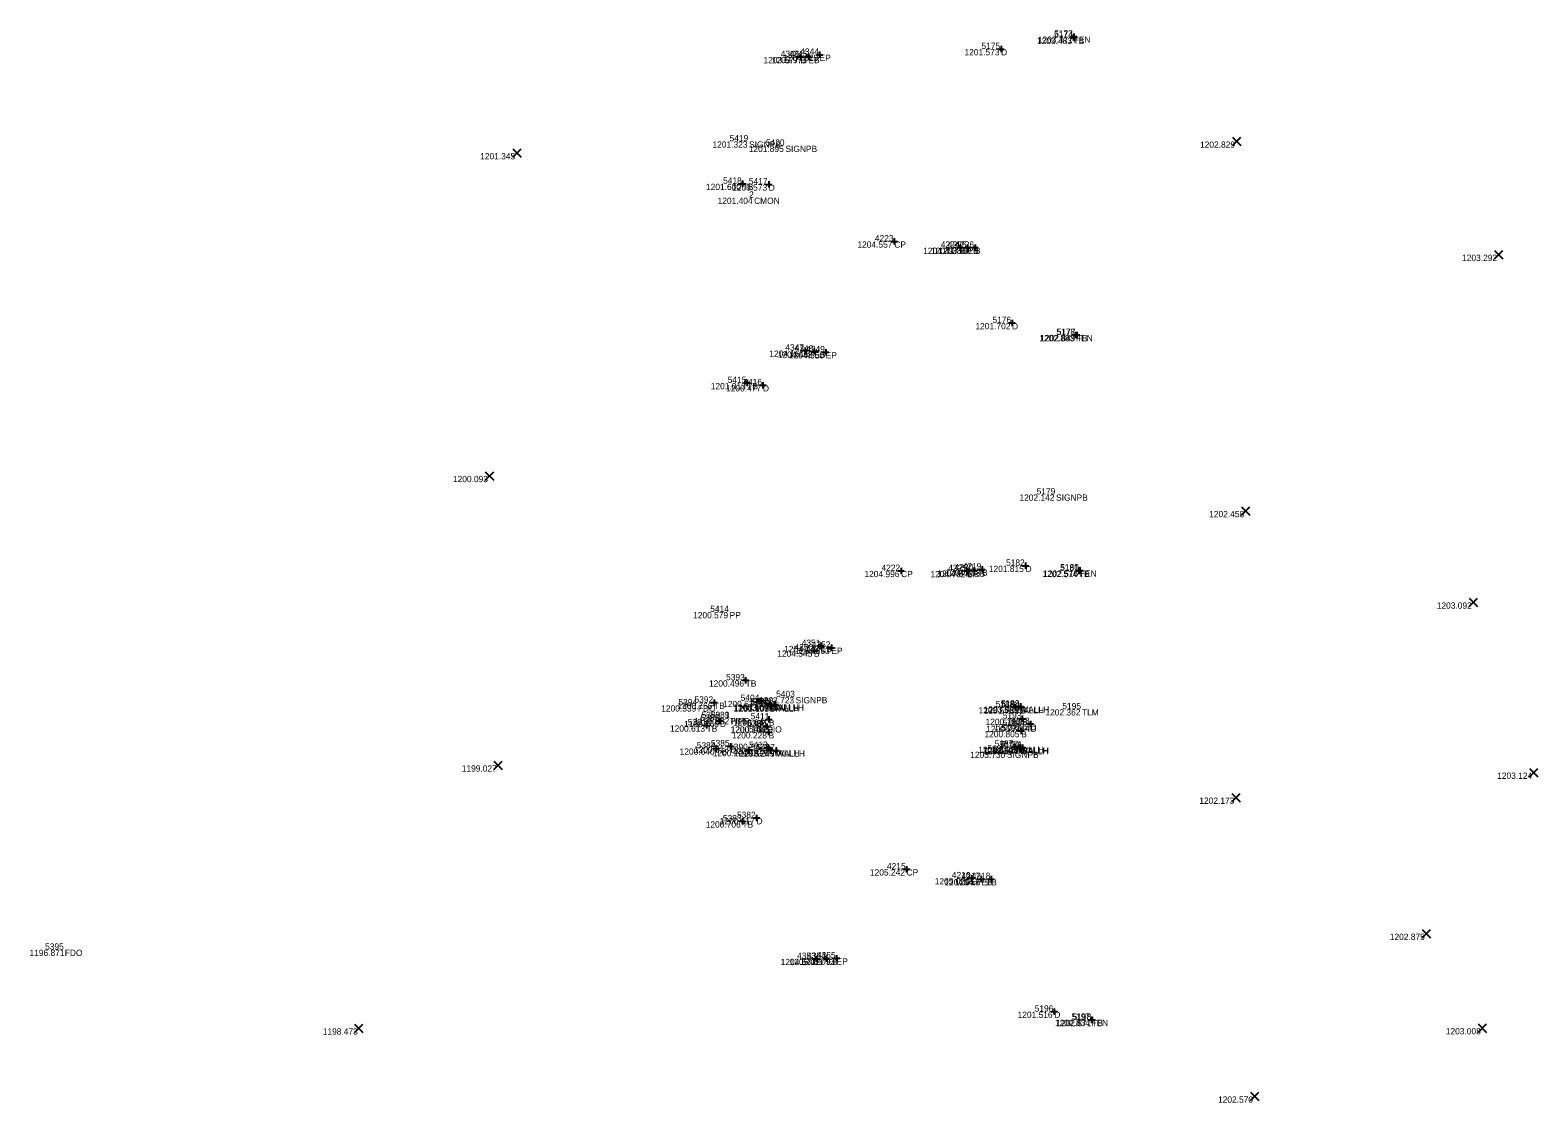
# Model space of a CAD drawing. Extents: x 2044997 to 2050342, y 455233 to 458054.
# Drawn here: x 2047488.9 to 2047729, y 457177 to 457347.8 of the extents above; entities that cross this region are included whole.
import ezdxf

# ---------------------------------------------------------------- set-up
doc = ezdxf.new("R2010")
doc.units = 0
for name, color, linetype in [('SV_X_Random_Point', 7, 'Continuous'), ('SV_X_Shot_Marker', 7, 'Continuous'), ('SV_X_Text_Comment', 7, 'Continuous'), ('SV_X_Text_Elevation', 7, 'Continuous'), ('SV_X_Text_Name', 7, 'Continuous')]:
    doc.layers.add(name, color=color, linetype=linetype)

msp = doc.modelspace()

# ---------------------------------------------------------------- linework, layer by layer
at = {"layer": 'SV_X_Random_Point'}
for p, q in [((2047680.37, 457329.41), (2047681.7, 457330.74)), ((2047680.37, 457330.74), (2047681.7, 457329.41)), ((2047565.73, 457327.55), (2047567.07, 457328.88)), ((2047565.73, 457328.88), (2047567.07, 457327.55)), ((2047722.14, 457311.4), (2047723.47, 457312.73)), ((2047722.14, 457312.73), (2047723.47, 457311.4)), ((2047561.37, 457276.15), (2047562.71, 457277.48)), ((2047561.37, 457277.48), (2047562.71, 457276.15)), ((2047681.85, 457270.57), (2047683.18, 457271.9)), ((2047681.85, 457271.9), (2047683.18, 457270.57)), ((2047718.1, 457256), (2047719.43, 457257.34)), ((2047718.1, 457257.34), (2047719.43, 457256)), ((2047562.72, 457230.05), (2047564.05, 457231.38)), ((2047562.72, 457231.38), (2047564.05, 457230.05)), ((2047727.7, 457228.9), (2047729.04, 457230.24)), ((2047727.7, 457230.24), (2047729.04, 457228.9)), ((2047680.27, 457224.92), (2047681.6, 457226.26)), ((2047680.27, 457226.26), (2047681.6, 457224.92)), ((2047710.63, 457203.24), (2047711.96, 457204.58)), ((2047710.63, 457204.58), (2047711.96, 457203.24)), ((2047540.53, 457188.16), (2047541.86, 457189.5)), ((2047540.53, 457189.5), (2047541.86, 457188.16)), ((2047719.54, 457188.2), (2047720.87, 457189.53)), ((2047719.54, 457189.53), (2047720.87, 457188.2)), ((2047683.26, 457177.32), (2047684.6, 457178.65)), ((2047683.26, 457178.65), (2047684.6, 457177.32))]:
    msp.add_line(p, q, dxfattribs=at)
at = {"layer": 'SV_X_Shot_Marker'}
for p, q in [((2047654.57, 457346.6), (2047655.57, 457346.6)), ((2047654.6, 457346.79), (2047655.6, 457346.79)), ((2047655.07, 457347.1), (2047655.07, 457346.1)), ((2047655.07, 457346.6), (2047655.07, 457346.6)), ((2047655.1, 457347.29), (2047655.1, 457346.29)), ((2047655.1, 457346.79), (2047655.1, 457346.79)), ((2047611.06, 457343.54), (2047612.06, 457343.54)), ((2047611.56, 457344.04), (2047611.56, 457343.04)), ((2047611.56, 457343.54), (2047611.56, 457343.54)), ((2047612.35, 457343.54), (2047613.35, 457343.54)), ((2047612.85, 457344.04), (2047612.85, 457343.04)), ((2047612.85, 457343.54), (2047612.85, 457343.54)), ((2047614.13, 457343.89), (2047615.13, 457343.89)), ((2047614.63, 457344.39), (2047614.63, 457343.39)), ((2047614.63, 457343.89), (2047614.63, 457343.89)), ((2047643.03, 457344.79), (2047644.03, 457344.79)), ((2047643.53, 457345.29), (2047643.53, 457344.29)), ((2047643.53, 457344.79), (2047643.53, 457344.79)), ((2047601.86, 457323.34), (2047602.86, 457323.34)), ((2047602.36, 457323.84), (2047602.36, 457322.84)), ((2047602.36, 457323.34), (2047602.36, 457323.34)), ((2047606.01, 457323.24), (2047607.01, 457323.24)), ((2047606.51, 457323.74), (2047606.51, 457322.74)), ((2047606.51, 457323.24), (2047606.51, 457323.24)), ((2047626.52, 457314.66), (2047626.52, 457313.66)), ((2047626.02, 457314.16), (2047627.02, 457314.16)), ((2047626.52, 457314.16), (2047626.52, 457314.16)), ((2047636.51, 457313.17), (2047637.51, 457313.17)), ((2047637.01, 457313.67), (2047637.01, 457312.67)), ((2047637.01, 457313.17), (2047637.01, 457313.17)), ((2047637.68, 457313.17), (2047638.68, 457313.17)), ((2047638.18, 457313.67), (2047638.18, 457312.67)), ((2047638.18, 457313.17), (2047638.18, 457313.17)), ((2047638.88, 457313.17), (2047639.88, 457313.17)), ((2047639.38, 457313.67), (2047639.38, 457312.67)), ((2047639.38, 457313.17), (2047639.38, 457313.17)), ((2047644.77, 457301.17), (2047645.77, 457301.17)), ((2047645.27, 457301.67), (2047645.27, 457300.67)), ((2047645.27, 457301.17), (2047645.27, 457301.17)), ((2047654.96, 457299.25), (2047655.96, 457299.25)), ((2047655.08, 457299.27), (2047656.08, 457299.27)), ((2047655.46, 457299.75), (2047655.46, 457298.75)), ((2047655.46, 457299.25), (2047655.46, 457299.25)), ((2047655.58, 457299.77), (2047655.58, 457298.77)), ((2047655.58, 457299.27), (2047655.58, 457299.27)), ((2047611.81, 457296.78), (2047612.81, 457296.78)), ((2047612.31, 457297.28), (2047612.31, 457296.28)), ((2047612.31, 457296.78), (2047612.31, 457296.78)), ((2047613.28, 457296.63), (2047614.28, 457296.63)), ((2047613.78, 457297.13), (2047613.78, 457296.13)), ((2047613.78, 457296.63), (2047613.78, 457296.63)), ((2047615.09, 457296.52), (2047616.09, 457296.52)), ((2047615.59, 457297.02), (2047615.59, 457296.02)), ((2047615.59, 457296.52), (2047615.59, 457296.52)), ((2047602.6, 457291.62), (2047603.6, 457291.62)), ((2047603.1, 457292.12), (2047603.1, 457291.12)), ((2047603.1, 457291.62), (2047603.1, 457291.62)), ((2047605.1, 457291.26), (2047606.1, 457291.26)), ((2047605.6, 457291.76), (2047605.6, 457290.76)), ((2047605.6, 457291.26), (2047605.6, 457291.26)), ((2047627.1, 457261.69), (2047628.1, 457261.69)), ((2047627.6, 457262.19), (2047627.6, 457261.19)), ((2047627.6, 457261.69), (2047627.6, 457261.69)), ((2047637.61, 457261.68), (2047638.61, 457261.68)), ((2047638.11, 457262.18), (2047638.11, 457261.18)), ((2047638.11, 457261.68), (2047638.11, 457261.68)), ((2047638.72, 457261.76), (2047639.72, 457261.76)), ((2047639.22, 457262.26), (2047639.22, 457261.26)), ((2047639.22, 457261.76), (2047639.22, 457261.76)), ((2047640, 457261.92), (2047641, 457261.92)), ((2047640.5, 457262.42), (2047640.5, 457261.42)), ((2047640.5, 457261.92), (2047640.5, 457261.92)), ((2047646.93, 457262.51), (2047647.93, 457262.51)), ((2047647.43, 457263.01), (2047647.43, 457262.01)), ((2047647.43, 457262.51), (2047647.43, 457262.51)), ((2047655.43, 457261.69), (2047656.43, 457261.69)), ((2047655.57, 457261.77), (2047656.57, 457261.77)), ((2047655.93, 457262.19), (2047655.93, 457261.19)), ((2047655.93, 457261.69), (2047655.93, 457261.69)), ((2047656.07, 457262.27), (2047656.07, 457261.27)), ((2047656.07, 457261.77), (2047656.07, 457261.77)), ((2047614.28, 457249.74), (2047615.28, 457249.74)), ((2047614.78, 457250.24), (2047614.78, 457249.24)), ((2047614.78, 457249.74), (2047614.78, 457249.74)), ((2047616.49, 457249.96), (2047616.49, 457248.96)), ((2047613.23, 457249.02), (2047614.23, 457249.02)), ((2047613.73, 457249.52), (2047613.73, 457248.52)), ((2047613.73, 457249.02), (2047613.73, 457249.02)), ((2047615.99, 457249.46), (2047616.99, 457249.46)), ((2047616.49, 457249.46), (2047616.49, 457249.46)), ((2047602.34, 457244.26), (2047603.34, 457244.26)), ((2047602.84, 457244.76), (2047602.84, 457243.76)), ((2047602.84, 457244.26), (2047602.84, 457244.26)), ((2047597.31, 457240.71), (2047598.31, 457240.71)), ((2047597.81, 457241.21), (2047597.81, 457240.21)), ((2047597.81, 457240.71), (2047597.81, 457240.71)), ((2047604.63, 457240.99), (2047605.63, 457240.99)), ((2047605.13, 457241.49), (2047605.13, 457240.49)), ((2047605.13, 457240.99), (2047605.13, 457240.99)), ((2047606.18, 457240.25), (2047607.18, 457240.25)), ((2047606.2, 457240.44), (2047607.2, 457240.44)), ((2047606.34, 457240.28), (2047607.34, 457240.28)), ((2047606.68, 457240.75), (2047606.68, 457239.75)), ((2047606.68, 457240.25), (2047606.68, 457240.25)), ((2047606.7, 457240.94), (2047606.7, 457239.94)), ((2047606.7, 457240.44), (2047606.7, 457240.44)), ((2047606.84, 457240.78), (2047606.84, 457239.78)), ((2047606.84, 457240.28), (2047606.84, 457240.28)), ((2047607.01, 457240.43), (2047608.01, 457240.43)), ((2047607.51, 457240.93), (2047607.51, 457239.93)), ((2047607.51, 457240.43), (2047607.51, 457240.43)), ((2047645.78, 457240.48), (2047645.78, 457239.48)), ((2047646.1, 457240.11), (2047647.1, 457240.11)), ((2047646.6, 457240.61), (2047646.6, 457239.61)), ((2047646.6, 457240.11), (2047646.6, 457240.11)), ((2047646.62, 457240.47), (2047646.62, 457239.47)), ((2047598.23, 457237.8), (2047599.23, 457237.8)), ((2047598.73, 457238.3), (2047598.73, 457237.3)), ((2047598.73, 457237.8), (2047598.73, 457237.8)), ((2047606.03, 457238.04), (2047607.03, 457238.04)), ((2047606.53, 457238.54), (2047606.53, 457237.54)), ((2047606.53, 457238.04), (2047606.53, 457238.04)), ((2047645.28, 457239.98), (2047646.28, 457239.98)), ((2047645.78, 457239.98), (2047645.78, 457239.98)), ((2047646.12, 457239.97), (2047647.12, 457239.97)), ((2047646.4, 457238.15), (2047647.4, 457238.15)), ((2047646.62, 457239.97), (2047646.62, 457239.97)), ((2047646.9, 457238.65), (2047646.9, 457237.65)), ((2047646.9, 457238.15), (2047646.9, 457238.15)), ((2047648.21, 457237.82), (2047648.21, 457236.82)), ((2047596.12, 457237.08), (2047597.12, 457237.08)), ((2047596.62, 457237.58), (2047596.62, 457236.58)), ((2047596.62, 457237.08), (2047596.62, 457237.08)), ((2047605.73, 457236.91), (2047606.73, 457236.91)), ((2047605.99, 457236), (2047606.99, 457236)), ((2047606.23, 457237.41), (2047606.23, 457236.41)), ((2047606.23, 457236.91), (2047606.23, 457236.91)), ((2047606.49, 457236.5), (2047606.49, 457235.5)), ((2047606.49, 457236), (2047606.49, 457236)), ((2047646.23, 457236.19), (2047647.23, 457236.19)), ((2047646.73, 457236.69), (2047646.73, 457235.69)), ((2047646.73, 457236.19), (2047646.73, 457236.19)), ((2047647.71, 457237.32), (2047648.71, 457237.32)), ((2047648.21, 457237.32), (2047648.21, 457237.32)), ((2047597.65, 457233.41), (2047598.65, 457233.41)), ((2047598.15, 457233.91), (2047598.15, 457232.91)), ((2047598.15, 457233.41), (2047598.15, 457233.41)), ((2047599.92, 457233.76), (2047600.92, 457233.76)), ((2047600.42, 457234.26), (2047600.42, 457233.26)), ((2047600.42, 457233.76), (2047600.42, 457233.76)), ((2047602.82, 457233.17), (2047603.82, 457233.17)), ((2047603.32, 457233.67), (2047603.32, 457232.67)), ((2047603.32, 457233.17), (2047603.32, 457233.17)), ((2047606, 457233.51), (2047607, 457233.51)), ((2047606.29, 457233.16), (2047607.29, 457233.16)), ((2047606.5, 457234.01), (2047606.5, 457233.01)), ((2047606.5, 457233.51), (2047606.5, 457233.51)), ((2047606.79, 457233.66), (2047606.79, 457232.66)), ((2047606.79, 457233.16), (2047606.79, 457233.16)), ((2047607.18, 457233.1), (2047608.18, 457233.1)), ((2047607.68, 457233.6), (2047607.68, 457232.6)), ((2047607.68, 457233.1), (2047607.68, 457233.1)), ((2047645.17, 457233.68), (2047646.17, 457233.68)), ((2047645.67, 457234.18), (2047645.67, 457233.18)), ((2047645.67, 457233.68), (2047645.67, 457233.68)), ((2047645.96, 457233.48), (2047646.96, 457233.48)), ((2047646.06, 457233.61), (2047647.06, 457233.61)), ((2047646.44, 457233.56), (2047647.44, 457233.56)), ((2047646.46, 457233.98), (2047646.46, 457232.98)), ((2047646.46, 457233.48), (2047646.46, 457233.48)), ((2047646.56, 457234.11), (2047646.56, 457233.11)), ((2047646.56, 457233.61), (2047646.56, 457233.61)), ((2047646.94, 457234.06), (2047646.94, 457233.06)), ((2047646.94, 457233.56), (2047646.94, 457233.56)), ((2047601.82, 457221.81), (2047602.82, 457221.81)), ((2047602.32, 457222.31), (2047602.32, 457221.31)), ((2047602.32, 457221.81), (2047602.32, 457221.81)), ((2047604.08, 457222.34), (2047605.08, 457222.34)), ((2047604.58, 457222.84), (2047604.58, 457221.84)), ((2047604.58, 457222.34), (2047604.58, 457222.34)), ((2047627.97, 457214.17), (2047628.97, 457214.17)), ((2047628.47, 457214.67), (2047628.47, 457213.67)), ((2047628.47, 457214.17), (2047628.47, 457214.17)), ((2047638.3, 457212.75), (2047639.3, 457212.75)), ((2047638.8, 457213.25), (2047638.8, 457212.25)), ((2047638.8, 457212.75), (2047638.8, 457212.75)), ((2047639.88, 457212.61), (2047640.88, 457212.61)), ((2047640.38, 457213.11), (2047640.38, 457212.11)), ((2047640.38, 457212.61), (2047640.38, 457212.61)), ((2047641.45, 457212.61), (2047642.45, 457212.61)), ((2047641.95, 457213.11), (2047641.95, 457212.11)), ((2047641.95, 457212.61), (2047641.95, 457212.61)), ((2047613.64, 457199.9), (2047614.64, 457199.9)), ((2047614.14, 457200.4), (2047614.14, 457199.4)), ((2047614.14, 457199.9), (2047614.14, 457199.9)), ((2047615.22, 457199.91), (2047616.22, 457199.91)), ((2047615.72, 457200.41), (2047615.72, 457199.41)), ((2047615.72, 457199.91), (2047615.72, 457199.91)), ((2047616.82, 457199.99), (2047617.82, 457199.99)), ((2047617.32, 457200.49), (2047617.32, 457199.49)), ((2047617.32, 457199.99), (2047617.32, 457199.99)), ((2047651.51, 457191.5), (2047652.51, 457191.5)), ((2047652.01, 457192), (2047652.01, 457191)), ((2047652.01, 457191.5), (2047652.01, 457191.5)), ((2047657.41, 457190.21), (2047658.41, 457190.21)), ((2047657.54, 457190.17), (2047658.54, 457190.17)), ((2047657.91, 457190.71), (2047657.91, 457189.71)), ((2047657.91, 457190.21), (2047657.91, 457190.21)), ((2047658.04, 457190.67), (2047658.04, 457189.67)), ((2047658.04, 457190.17), (2047658.04, 457190.17))]:
    msp.add_line(p, q, dxfattribs=at)

# ---------------------------------------------------------------- texts
at = {"layer": 'SV_X_Text_Comment'}
for s, p in [('TB', (2047655.07, 457345.6)), ('FEN', (2047655.1, 457345.79)), ('B', (2047611.56, 457342.54)), ('EB', (2047612.85, 457342.54)), ('EP', (2047614.63, 457342.89)), ('D', (2047643.53, 457343.79)), ('SIGNPB', (2047603.38, 457329.09)), ('SIGNPB', (2047609.18, 457328.4)), ('TB', (2047602.36, 457322.34)), ('D', (2047606.51, 457322.24)), ('CMON', (2047604.18, 457320.13)), ('CP', (2047626.52, 457313.16)), ('EP', (2047637.01, 457312.17)), ('EB', (2047638.18, 457312.17)), ('B', (2047639.38, 457312.17)), ('D', (2047645.27, 457300.17)), ('FEN', (2047655.46, 457298.25)), ('TB', (2047655.58, 457298.27)), ('B', (2047612.31, 457295.78)), ('EB', (2047613.78, 457295.63)), ('EP', (2047615.59, 457295.52)), ('TB', (2047603.1, 457290.62)), ('D', (2047605.6, 457290.26)), ('SIGNPB', (2047652.29, 457272.86)), ('CP', (2047627.6, 457260.69)), ('EP', (2047638.11, 457260.68)), ('EB', (2047639.22, 457260.76)), ('B', (2047640.5, 457260.92)), ('D', (2047647.43, 457261.51)), ('TB', (2047655.93, 457260.69)), ('FEN', (2047656.07, 457260.77)), ('PP', (2047600.29, 457254.14)), ('EB', (2047614.78, 457248.74)), ('B', (2047613.73, 457248.02)), ('EP', (2047616.49, 457248.46)), ('TB', (2047602.84, 457243.26)), ('FDO', (2047595.22, 457239.29)), ('TB', (2047597.81, 457239.71)), ('D', (2047605.13, 457239.99)), ('WALLH', (2047606.7, 457239.44)), ('B', (2047606.68, 457239.25)), ('WALLH', (2047606.84, 457239.28)), ('WALLH', (2047607.51, 457239.43)), ('SIGNPB', (2047610.8, 457240.59)), ('WALLH', (2047646.6, 457239.11)), ('D', (2047598.73, 457236.8)), ('TILE', (2047600.38, 457237.27)), ('PIPE', (2047600.38, 457237.27)), ('B', (2047606.53, 457237.04)), ('WALLH', (2047645.78, 457238.98)), ('B', (2047646.62, 457238.97)), ('B', (2047646.9, 457237.15)), ('TLM', (2047656.42, 457238.66)), ('TB', (2047596.62, 457236.08)), ('D', (2047606.23, 457235.91)), ('PIO', (2047606.29, 457235.94)), ('B', (2047606.49, 457235)), ('B', (2047646.73, 457235.19)), ('PIO', (2047646.88, 457236.02)), ('D', (2047648.21, 457236.32)), ('TB', (2047598.15, 457232.41)), ('D', (2047600.42, 457232.76)), ('TB', (2047603.32, 457232.17)), ('B', (2047606.5, 457232.51)), ('WALLH', (2047606.79, 457232.16)), ('WALLH', (2047607.68, 457232.1)), ('SIGNPB', (2047644.46, 457231.9)), ('WALLH', (2047645.67, 457232.68)), ('WALLH', (2047646.46, 457232.48)), ('WALLH', (2047646.56, 457232.61)), ('B', (2047646.94, 457232.56)), ('TB', (2047602.32, 457220.81)), ('D', (2047604.58, 457221.34)), ('CP', (2047628.47, 457213.17)), ('EP', (2047638.8, 457211.75)), ('EB', (2047640.38, 457211.61)), ('B', (2047641.95, 457211.61)), ('FDO', (2047494.37, 457200.36)), ('B', (2047614.14, 457198.9)), ('EB', (2047615.72, 457198.91)), ('EP', (2047617.32, 457198.99)), ('D', (2047652.01, 457190.5)), ('FEN', (2047657.91, 457189.21)), ('TB', (2047658.04, 457189.17))]:
    msp.add_text(s, height=1, dxfattribs=at).set_placement(p)
at = {"layer": 'SV_X_Text_Elevation'}
for s, p in [('1203.483', (2047649.25, 457345.6)), ('1203.471', (2047649.38, 457345.79)), ('1203.577', (2047605.68, 457342.54)), ('1203.973', (2047607.02, 457342.54)), ('1204.029', (2047608.81, 457342.89)), ('1201.573', (2047637.7, 457343.79)), ('1201.323', (2047597.56, 457329.09)), ('1201.895', (2047603.33, 457328.4)), ('1202.829', (2047675.22, 457329.07)), ('1201.345', (2047560.55, 457327.22)), ('1201.600', (2047596.52, 457322.34)), ('1200.573', (2047600.69, 457322.24)), ('1201.404', (2047598.37, 457320.13)), ('1204.557', (2047620.64, 457313.16)), ('1204.397', (2047631.13, 457312.17)), ('1204.284', (2047632.37, 457312.17)), ('1203.892', (2047633.54, 457312.17)), ('1203.292', (2047716.97, 457311.06)), ('1201.702', (2047639.44, 457300.17)), ('1202.883', (2047649.63, 457298.25)), ('1202.849', (2047649.77, 457298.27)), ('1204.161', (2047606.6, 457295.78)), ('1204.468', (2047607.95, 457295.63)), ('1204.550', (2047609.75, 457295.52)), ('1201.013', (2047597.28, 457290.62)), ('1200.477', (2047599.72, 457290.26)), ('1200.093', (2047556.21, 457275.82)), ('1202.142', (2047646.45, 457272.86)), ('1202.458', (2047676.68, 457270.24)), ('1204.996', (2047621.76, 457260.69)), ('1204.762', (2047632.28, 457260.68)), ('1204.646', (2047633.38, 457260.76)), ('1204.393', (2047634.68, 457260.92)), ('1201.815', (2047641.58, 457261.51)), ('1202.574', (2047650.12, 457260.69)), ('1202.516', (2047650.23, 457260.77)), ('1200.579', (2047594.47, 457254.14)), ('1203.092', (2047712.93, 457255.67)), ('1204.773', (2047608.96, 457248.74)), ('1204.545', (2047607.88, 457248.02)), ('1204.853', (2047610.67, 457248.46)), ('1200.496', (2047597, 457243.26)), ('1200.339', (2047589.4, 457239.29)), ('1200.766', (2047591.97, 457239.71)), ('1200.677', (2047599.25, 457239.99)), ('1203.109', (2047600.88, 457239.44)), ('1201.001', (2047600.96, 457239.25)), ('1203.109', (2047601.02, 457239.28)), ('1203.092', (2047601.68, 457239.43)), ('1203.723', (2047604.98, 457240.59)), ('1203.525', (2047640.75, 457239.11)), ('1198.769', (2047593.02, 457236.8)), ('1198.832', (2047594.65, 457237.27)), ('1198.832', (2047594.65, 457237.27)), ('1200.641', (2047600.81, 457237.04)), ('1203.556', (2047639.94, 457238.98)), ('1201.788', (2047640.79, 457238.97)), ('1200.760', (2047641.06, 457237.15)), ('1202.362', (2047650.59, 457238.66)), ('1200.613', (2047590.79, 457236.08)), ('1200.144', (2047600.42, 457235.91)), ('1200.169', (2047600.47, 457235.94)), ('1200.228', (2047600.65, 457235)), ('1200.805', (2047640.88, 457235.19)), ('1200.771', (2047641.16, 457236.02)), ('1200.882', (2047642.38, 457236.32)), ('1200.640', (2047592.32, 457232.41)), ('1200.313', (2047594.6, 457232.76)), ('1200.201', (2047597.6, 457232.17)), ('1201.115', (2047600.76, 457232.51)), ('1203.125', (2047600.94, 457232.16)), ('1203.243', (2047601.86, 457232.1)), ('1203.730', (2047638.62, 457231.9)), ('1203.544', (2047639.87, 457232.68)), ('1203.504', (2047640.65, 457232.48)), ('1203.528', (2047640.73, 457232.61)), ('1201.446', (2047641.1, 457232.56)), ('1199.027', (2047557.61, 457229.72)), ('1203.124', (2047722.56, 457228.57)), ('1202.173', (2047675.11, 457224.59)), ('1200.706', (2047596.48, 457220.81)), ('1200.617', (2047598.7, 457221.34)), ('1205.242', (2047622.64, 457213.17)), ('1205.020', (2047632.96, 457211.75)), ('1204.957', (2047634.5, 457211.61)), ('1204.679', (2047636.14, 457211.61)), ('1202.875', (2047705.45, 457202.91)), ('1196.871', (2047488.76, 457200.36)), ('1204.571', (2047608.42, 457198.9)), ('1205.027', (2047609.84, 457198.91)), ('1205.093', (2047611.5, 457198.99)), ('1201.516', (2047646.16, 457190.5)), ('1202.834', (2047652.11, 457189.21)), ('1202.871', (2047652.32, 457189.17)), ('1198.473', (2047535.47, 457187.83)), ('1203.008', (2047714.37, 457187.87)), ('1202.570', (2047678.09, 457176.99))]:
    msp.add_text(s, height=1, dxfattribs=at).set_placement(p)
at = {"layer": 'SV_X_Text_Name'}
for s, p in [('5175', (2047640.4, 457344.79)), ('5174', (2047651.98, 457346.6)), ('5173', (2047651.99, 457346.79)), ('4346', (2047608.44, 457343.54)), ('4345', (2047609.72, 457343.54)), ('4344', (2047611.54, 457343.89)), ('5419', (2047600.28, 457330.09)), ('5420', (2047606.06, 457329.4)), ('5418', (2047599.24, 457323.34)), ('5417', (2047603.35, 457323.24)), ('2', (2047603.39, 457321.13)), ('4223', (2047623.42, 457314.16)), ('4224', (2047633.92, 457313.17)), ('4225', (2047635.05, 457313.17)), ('4226', (2047636.25, 457313.17)), ('5176', (2047642.15, 457301.17)), ('5178', (2047652.34, 457299.25)), ('5177', (2047652.42, 457299.27)), ('4347', (2047609.15, 457296.78)), ('4348', (2047610.66, 457296.63)), ('4349', (2047612.49, 457296.52)), ('5415', (2047599.97, 457291.62)), ('5416', (2047602.47, 457291.26)), ('5179', (2047649.19, 457273.86)), ('4222', (2047624.48, 457261.69)), ('4221', (2047635.11, 457261.68)), ('4220', (2047636.1, 457261.76)), ('4219', (2047637.4, 457261.92)), ('5182', (2047644.32, 457262.51)), ('5181', (2047652.93, 457261.69)), ('5180', (2047652.95, 457261.77)), ('5414', (2047597.2, 457255.14)), ('4350', (2047610.61, 457249.02)), ('4351', (2047611.78, 457249.74)), ('4352', (2047613.38, 457249.46)), ('5393', (2047599.73, 457244.26)), ('5403', (2047607.7, 457241.59)), ('5394', (2047592.13, 457240.29)), ('5392', (2047594.69, 457240.71)), ('5404', (2047602.04, 457240.99)), ('5405', (2047603.57, 457240.44)), ('5410', (2047603.56, 457240.25)), ('5409', (2047603.74, 457240.28)), ('5406', (2047604.39, 457240.43)), ('5188', (2047642.66, 457239.98)), ('5189', (2047643.5, 457240.11)), ('5194', (2047643.53, 457239.97)), ('5195', (2047653.29, 457239.66)), ('5391', (2047593.62, 457237.08)), ('5388', (2047595.61, 457237.8)), ('5389_1', (2047595.82, 457238.27)), ('5389', (2047597.28, 457238.27)), ('5387', (2047603.07, 457236.91)), ('5386', (2047603.17, 457236.94)), ('5411', (2047603.64, 457238.04)), ('5193', (2047643.79, 457238.15)), ('5184', (2047643.79, 457237.02)), ('5183', (2047645.1, 457237.32)), ('5412', (2047603.37, 457236)), ('5192', (2047643.61, 457236.19)), ('5384', (2047595.06, 457233.41)), ('5385', (2047597.3, 457233.76)), ('5390', (2047600.2, 457233.17)), ('5413', (2047603.39, 457233.51)), ('5408', (2047603.67, 457233.16)), ('5407', (2047604.52, 457233.1)), ('5185', (2047641.33, 457232.9)), ('5187', (2047642.51, 457233.68)), ('5186', (2047643.34, 457233.48)), ('5190', (2047643.44, 457233.61)), ('5191', (2047643.94, 457233.56)), ('5382', (2047601.46, 457222.34)), ('5383', (2047599.21, 457221.81)), ('4215', (2047625.35, 457214.17)), ('4216', (2047635.68, 457212.75)), ('4217', (2047637.22, 457212.61)), ('4218', (2047638.84, 457212.61)), ('5395', (2047491.24, 457201.36)), ('4353', (2047611.03, 457199.9)), ('4354', (2047612.63, 457199.91)), ('4355', (2047614.19, 457199.99)), ('5196', (2047648.88, 457191.5)), ('5197', (2047654.75, 457190.21)), ('5198', (2047654.92, 457190.17))]:
    msp.add_text(s, height=1, dxfattribs=at).set_placement(p)

doc.saveas('drawing.dxf')
